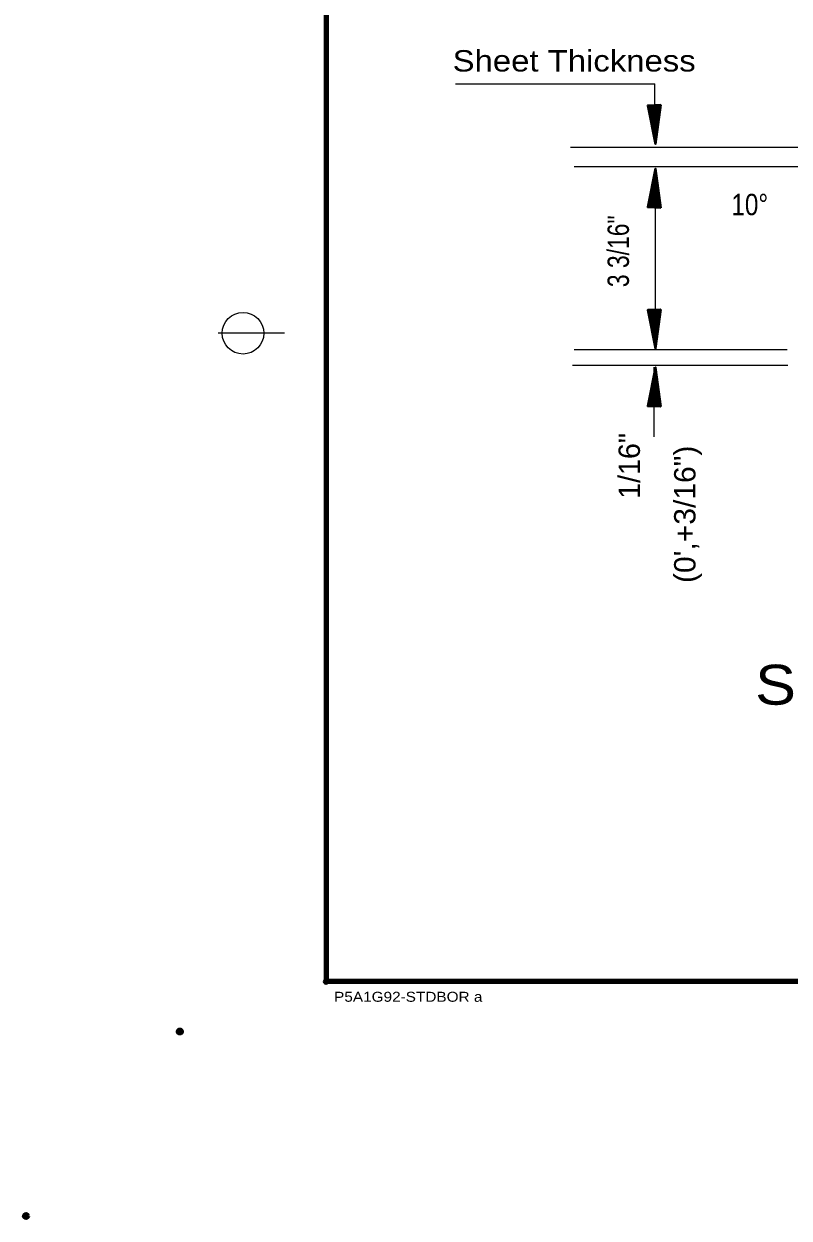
# Model space of a CAD drawing. Extents: x 895.6 to 930.4, y -2278.6 to -2254.7.
# Drawn here: x 895.62 to 900.23, y -2278.59 to -2271.4 of the extents above; entities that cross this region are included whole.
import ezdxf

# ---------------------------------------------------------------- set-up
doc = ezdxf.new("R2010")
doc.units = 0
doc.header["$LTSCALE"] = 0.051
doc.header["$PDMODE"] = 32
doc.header["$PDSIZE"] = 0.0255
doc.layers.add('1', color=7, linetype='Continuous', lineweight=70)
doc.layers.add('3', color=7, linetype='Continuous', lineweight=40)

msp = doc.modelspace()

# ---------------------------------------------------------------- hatches: boundary and pattern name
at = {"layer": '3'}
for points in [[(899.4545, -2271.89058), (899.3765, -2271.89325), (899.42342, -2272.12592), (899.42342, -2272.12592)], [(899.45058, -2271.89183), (899.38042, -2271.89417), (899.42258, -2272.1035), (899.42258, -2272.1035)], [(899.44708, -2271.89283), (899.384, -2271.895), (899.422, -2272.08342), (899.422, -2272.08342)], [(899.444, -2271.89383), (899.38725, -2271.89575), (899.42142, -2272.06533), (899.42142, -2272.06533)], [(899.44133, -2271.89458), (899.39017, -2271.89642), (899.42092, -2272.04908), (899.42092, -2272.04908)], [(899.43867, -2271.89558), (899.39267, -2271.89708), (899.42042, -2272.03442), (899.42042, -2272.03442)], [(899.43633, -2271.89617), (899.39492, -2271.8975), (899.41992, -2272.02125), (899.41992, -2272.02125)], [(899.43442, -2271.89692), (899.39708, -2271.898), (899.41958, -2272.00925), (899.41958, -2272.00925)], [(899.43258, -2271.89725), (899.39892, -2271.89858), (899.41908, -2271.99867), (899.41908, -2271.99867)], [(899.43083, -2271.89792), (899.4005, -2271.899), (899.41883, -2271.989), (899.41883, -2271.989)], [(899.42933, -2271.89842), (899.40217, -2271.89933), (899.4185, -2271.98033), (899.4185, -2271.98033)], [(899.42792, -2271.89875), (899.40358, -2271.89967), (899.41817, -2271.97258), (899.41817, -2271.97258)], [(899.42683, -2271.89925), (899.40475, -2271.89992), (899.418, -2271.96542), (899.418, -2271.96542)], [(899.42567, -2271.89967), (899.40583, -2271.90017), (899.41783, -2271.95933), (899.41783, -2271.95933)], [(899.42475, -2271.89992), (899.40683, -2271.9005), (899.41767, -2271.95358), (899.41767, -2271.95358)], [(899.42383, -2271.90017), (899.40767, -2271.90058), (899.41733, -2271.9485), (899.41733, -2271.9485)], [(899.423, -2271.90042), (899.40842, -2271.90092), (899.41717, -2271.94392), (899.41717, -2271.94392)], [(899.42225, -2271.90058), (899.40925, -2271.901), (899.41708, -2271.93983), (899.41708, -2271.93983)], [(899.42183, -2271.90092), (899.41, -2271.90117), (899.41708, -2271.93617), (899.41708, -2271.93617)], [(899.42125, -2271.90108), (899.41067, -2271.90142), (899.417, -2271.93292), (899.417, -2271.93292)], [(899.42092, -2271.90133), (899.41133, -2271.90167), (899.41717, -2271.92992), (899.41717, -2271.92992)], [(899.42033, -2271.90133), (899.41183, -2271.90167), (899.417, -2271.92717), (899.417, -2271.92717)], [(899.41983, -2271.9015), (899.41225, -2271.90183), (899.41675, -2271.92475), (899.41675, -2271.92475)], [(899.41958, -2271.90167), (899.41275, -2271.90192), (899.41683, -2271.92258), (899.41683, -2271.92258)], [(899.4545, -2272.50825), (899.3765, -2272.50558), (899.42342, -2272.27292), (899.42342, -2272.27292)], [(899.45058, -2272.507), (899.38042, -2272.50467), (899.42258, -2272.29533), (899.42258, -2272.29533)], [(899.44708, -2272.506), (899.384, -2272.50383), (899.422, -2272.31542), (899.422, -2272.31542)], [(899.444, -2272.505), (899.38725, -2272.50308), (899.42142, -2272.3335), (899.42142, -2272.3335)], [(899.44133, -2272.50425), (899.39017, -2272.50242), (899.42092, -2272.34975), (899.42092, -2272.34975)], [(899.43867, -2272.50325), (899.39267, -2272.50175), (899.42042, -2272.36442), (899.42042, -2272.36442)], [(899.43633, -2272.50267), (899.39492, -2272.50133), (899.41992, -2272.37758), (899.41992, -2272.37758)], [(899.43442, -2272.50192), (899.39708, -2272.50083), (899.41958, -2272.38958), (899.41958, -2272.38958)], [(899.43258, -2272.50158), (899.39892, -2272.50025), (899.41908, -2272.40017), (899.41908, -2272.40017)], [(899.43083, -2272.50092), (899.4005, -2272.49983), (899.41883, -2272.40983), (899.41883, -2272.40983)], [(899.42933, -2272.50042), (899.40217, -2272.4995), (899.4185, -2272.4185), (899.4185, -2272.4185)], [(899.42792, -2272.50008), (899.40358, -2272.49917), (899.41817, -2272.42625), (899.41817, -2272.42625)], [(899.42683, -2272.49958), (899.40475, -2272.49892), (899.418, -2272.43342), (899.418, -2272.43342)], [(899.42567, -2272.49917), (899.40583, -2272.49867), (899.41783, -2272.4395), (899.41783, -2272.4395)], [(899.42475, -2272.49892), (899.40683, -2272.49833), (899.41767, -2272.44525), (899.41767, -2272.44525)], [(899.42383, -2272.49867), (899.40767, -2272.49825), (899.41733, -2272.45033), (899.41733, -2272.45033)], [(899.423, -2272.49842), (899.40842, -2272.49792), (899.41717, -2272.45492), (899.41717, -2272.45492)], [(899.42225, -2272.49825), (899.40925, -2272.49783), (899.41708, -2272.459), (899.41708, -2272.459)], [(899.42183, -2272.49792), (899.41, -2272.49767), (899.41708, -2272.46267), (899.41708, -2272.46267)], [(899.42125, -2272.49775), (899.41067, -2272.49742), (899.417, -2272.46592), (899.417, -2272.46592)], [(899.42092, -2272.4975), (899.41133, -2272.49717), (899.41717, -2272.46892), (899.41717, -2272.46892)], [(899.42033, -2272.4975), (899.41183, -2272.49717), (899.417, -2272.47167), (899.417, -2272.47167)], [(899.41983, -2272.49733), (899.41225, -2272.497), (899.41675, -2272.47408), (899.41675, -2272.47408)], [(899.41958, -2272.49717), (899.41275, -2272.49692), (899.41683, -2272.47625), (899.41683, -2272.47625)], [(899.4545, -2273.12025), (899.3765, -2273.12292), (899.42342, -2273.35558), (899.42342, -2273.35558)], [(899.45058, -2273.1215), (899.38042, -2273.12383), (899.42258, -2273.33317), (899.42258, -2273.33317)], [(899.44708, -2273.1225), (899.384, -2273.12467), (899.422, -2273.31308), (899.422, -2273.31308)], [(899.444, -2273.1235), (899.38725, -2273.12542), (899.42142, -2273.295), (899.42142, -2273.295)], [(899.44133, -2273.12425), (899.39017, -2273.12608), (899.42092, -2273.27875), (899.42092, -2273.27875)], [(899.43867, -2273.12525), (899.39267, -2273.12675), (899.42042, -2273.26408), (899.42042, -2273.26408)], [(899.43633, -2273.12583), (899.39492, -2273.12717), (899.41992, -2273.25092), (899.41992, -2273.25092)], [(899.43442, -2273.12658), (899.39708, -2273.12767), (899.41958, -2273.23892), (899.41958, -2273.23892)], [(899.43258, -2273.12692), (899.39892, -2273.12825), (899.41908, -2273.22833), (899.41908, -2273.22833)], [(899.43083, -2273.12758), (899.4005, -2273.12867), (899.41883, -2273.21867), (899.41883, -2273.21867)], [(899.42933, -2273.12808), (899.40217, -2273.129), (899.4185, -2273.21), (899.4185, -2273.21)], [(899.42792, -2273.12842), (899.40358, -2273.12933), (899.41817, -2273.20225), (899.41817, -2273.20225)], [(899.42683, -2273.12892), (899.40475, -2273.12958), (899.418, -2273.19508), (899.418, -2273.19508)], [(899.42567, -2273.12933), (899.40583, -2273.12983), (899.41783, -2273.189), (899.41783, -2273.189)], [(899.42475, -2273.12958), (899.40683, -2273.13017), (899.41767, -2273.18325), (899.41767, -2273.18325)], [(899.42383, -2273.12983), (899.40767, -2273.13025), (899.41733, -2273.17817), (899.41733, -2273.17817)], [(899.423, -2273.13008), (899.40842, -2273.13058), (899.41717, -2273.17358), (899.41717, -2273.17358)], [(899.42225, -2273.13025), (899.40925, -2273.13067), (899.41708, -2273.1695), (899.41708, -2273.1695)], [(899.42183, -2273.13058), (899.41, -2273.13083), (899.41708, -2273.16583), (899.41708, -2273.16583)], [(899.42125, -2273.13075), (899.41067, -2273.13108), (899.417, -2273.16258), (899.417, -2273.16258)], [(899.42092, -2273.131), (899.41133, -2273.13133), (899.41717, -2273.15958), (899.41717, -2273.15958)], [(899.42033, -2273.131), (899.41183, -2273.13133), (899.417, -2273.15683), (899.417, -2273.15683)], [(899.41983, -2273.13117), (899.41225, -2273.1315), (899.41675, -2273.15442), (899.41675, -2273.15442)], [(899.41958, -2273.13133), (899.41275, -2273.13158), (899.41683, -2273.15225), (899.41683, -2273.15225)], [(899.4545, -2273.70475), (899.3765, -2273.70208), (899.42342, -2273.46942), (899.42342, -2273.46942)], [(899.45058, -2273.7035), (899.38042, -2273.70117), (899.42258, -2273.49183), (899.42258, -2273.49183)], [(899.44708, -2273.7025), (899.384, -2273.70033), (899.422, -2273.51192), (899.422, -2273.51192)], [(899.444, -2273.7015), (899.38725, -2273.69958), (899.42142, -2273.53), (899.42142, -2273.53)], [(899.44133, -2273.70075), (899.39017, -2273.69892), (899.42092, -2273.54625), (899.42092, -2273.54625)], [(899.43867, -2273.69975), (899.39267, -2273.69825), (899.42042, -2273.56092), (899.42042, -2273.56092)], [(899.43633, -2273.69917), (899.39492, -2273.69783), (899.41992, -2273.57408), (899.41992, -2273.57408)], [(899.43442, -2273.69842), (899.39708, -2273.69733), (899.41958, -2273.58608), (899.41958, -2273.58608)], [(899.43258, -2273.69808), (899.39892, -2273.69675), (899.41908, -2273.59667), (899.41908, -2273.59667)], [(899.43083, -2273.69742), (899.4005, -2273.69633), (899.41883, -2273.60633), (899.41883, -2273.60633)], [(899.42933, -2273.69692), (899.40217, -2273.696), (899.4185, -2273.615), (899.4185, -2273.615)], [(899.42792, -2273.69658), (899.40358, -2273.69567), (899.41817, -2273.62275), (899.41817, -2273.62275)], [(899.42683, -2273.69608), (899.40475, -2273.69542), (899.418, -2273.62992), (899.418, -2273.62992)], [(899.42567, -2273.69567), (899.40583, -2273.69517), (899.41783, -2273.636), (899.41783, -2273.636)], [(899.42475, -2273.69542), (899.40683, -2273.69483), (899.41767, -2273.64175), (899.41767, -2273.64175)], [(899.42383, -2273.69517), (899.40767, -2273.69475), (899.41733, -2273.64683), (899.41733, -2273.64683)], [(899.423, -2273.69492), (899.40842, -2273.69442), (899.41717, -2273.65142), (899.41717, -2273.65142)], [(899.42225, -2273.69475), (899.40925, -2273.69433), (899.41708, -2273.6555), (899.41708, -2273.6555)], [(899.42183, -2273.69442), (899.41, -2273.69417), (899.41708, -2273.65917), (899.41708, -2273.65917)], [(899.42125, -2273.69425), (899.41067, -2273.69392), (899.417, -2273.66242), (899.417, -2273.66242)], [(899.42092, -2273.694), (899.41133, -2273.69367), (899.41717, -2273.66542), (899.41717, -2273.66542)], [(899.42033, -2273.694), (899.41183, -2273.69367), (899.417, -2273.66817), (899.417, -2273.66817)], [(899.41983, -2273.69383), (899.41225, -2273.6935), (899.41675, -2273.67058), (899.41675, -2273.67058)], [(899.41958, -2273.69367), (899.41275, -2273.69342), (899.41683, -2273.67275), (899.41683, -2273.67275)]]:
    msp.add_hatch(color=256, dxfattribs=at).paths.add_polyline_path(points)

# ---------------------------------------------------------------- linework, layer by layer
at = {"layer": '1', "lineweight": 25}
for p, q in [((898.22108, -2271.76283), (899.41933, -2271.76283)), ((899.41933, -2272.12292), (899.41933, -2271.76283)), ((898.91175, -2272.14508), (900.7885, -2272.14508)), ((898.93392, -2272.26058), (900.6745, -2272.26058)), ((899.42375, -2273.33025), (899.42375, -2272.28775)), ((898.93392, -2273.36142), (900.21608, -2273.36142)), ((898.92433, -2273.45467), (900.21842, -2273.45467)), ((899.41483, -2273.88717), (899.41483, -2273.46842))]:
    msp.add_line(p, q, dxfattribs=at)
at = {"layer": '1'}
for p in [(896.56183, -2277.46333), (895.63642, -2278.57275)]:
    msp.add_point(p, dxfattribs=at)
at = {"layer": '3', "lineweight": 158}
msp.add_line((897.44183, -2256.16333), (897.44183, -2277.16333), dxfattribs=at)
at = {"layer": '3', "lineweight": 13}
msp.add_line((897.19183, -2273.26333), (896.79183, -2273.26333), dxfattribs=at)
at = {"layer": '3', "lineweight": 158}
msp.add_lwpolyline([(929.94183, -2256.16333), (929.94183, -2277.16333), (897.44183, -2277.16333)], dxfattribs=at)
at = {"layer": '3'}
for points in [[(899.4545, -2271.89058), (899.3765, -2271.89325), (899.42342, -2272.12592), (899.42342, -2272.12592)], [(899.45058, -2271.89183), (899.38042, -2271.89417), (899.42258, -2272.1035), (899.42258, -2272.1035)], [(899.44708, -2271.89283), (899.384, -2271.895), (899.422, -2272.08342), (899.422, -2272.08342)], [(899.444, -2271.89383), (899.38725, -2271.89575), (899.42142, -2272.06533), (899.42142, -2272.06533)], [(899.44133, -2271.89458), (899.39017, -2271.89642), (899.42092, -2272.04908), (899.42092, -2272.04908)], [(899.43867, -2271.89558), (899.39267, -2271.89708), (899.42042, -2272.03442), (899.42042, -2272.03442)], [(899.43633, -2271.89617), (899.39492, -2271.8975), (899.41992, -2272.02125), (899.41992, -2272.02125)], [(899.43442, -2271.89692), (899.39708, -2271.898), (899.41958, -2272.00925), (899.41958, -2272.00925)], [(899.43258, -2271.89725), (899.39892, -2271.89858), (899.41908, -2271.99867), (899.41908, -2271.99867)], [(899.43083, -2271.89792), (899.4005, -2271.899), (899.41883, -2271.989), (899.41883, -2271.989)], [(899.42933, -2271.89842), (899.40217, -2271.89933), (899.4185, -2271.98033), (899.4185, -2271.98033)], [(899.42792, -2271.89875), (899.40358, -2271.89967), (899.41817, -2271.97258), (899.41817, -2271.97258)], [(899.42683, -2271.89925), (899.40475, -2271.89992), (899.418, -2271.96542), (899.418, -2271.96542)], [(899.42567, -2271.89967), (899.40583, -2271.90017), (899.41783, -2271.95933), (899.41783, -2271.95933)], [(899.42475, -2271.89992), (899.40683, -2271.9005), (899.41767, -2271.95358), (899.41767, -2271.95358)], [(899.42383, -2271.90017), (899.40767, -2271.90058), (899.41733, -2271.9485), (899.41733, -2271.9485)], [(899.423, -2271.90042), (899.40842, -2271.90092), (899.41717, -2271.94392), (899.41717, -2271.94392)], [(899.42225, -2271.90058), (899.40925, -2271.901), (899.41708, -2271.93983), (899.41708, -2271.93983)], [(899.42183, -2271.90092), (899.41, -2271.90117), (899.41708, -2271.93617), (899.41708, -2271.93617)], [(899.42125, -2271.90108), (899.41067, -2271.90142), (899.417, -2271.93292), (899.417, -2271.93292)], [(899.42092, -2271.90133), (899.41133, -2271.90167), (899.41717, -2271.92992), (899.41717, -2271.92992)], [(899.42033, -2271.90133), (899.41183, -2271.90167), (899.417, -2271.92717), (899.417, -2271.92717)], [(899.41983, -2271.9015), (899.41225, -2271.90183), (899.41675, -2271.92475), (899.41675, -2271.92475)], [(899.41958, -2271.90167), (899.41275, -2271.90192), (899.41683, -2271.92258), (899.41683, -2271.92258)], [(899.4545, -2272.50825), (899.3765, -2272.50558), (899.42342, -2272.27292), (899.42342, -2272.27292)], [(899.45058, -2272.507), (899.38042, -2272.50467), (899.42258, -2272.29533), (899.42258, -2272.29533)], [(899.44708, -2272.506), (899.384, -2272.50383), (899.422, -2272.31542), (899.422, -2272.31542)], [(899.444, -2272.505), (899.38725, -2272.50308), (899.42142, -2272.3335), (899.42142, -2272.3335)], [(899.44133, -2272.50425), (899.39017, -2272.50242), (899.42092, -2272.34975), (899.42092, -2272.34975)], [(899.43867, -2272.50325), (899.39267, -2272.50175), (899.42042, -2272.36442), (899.42042, -2272.36442)], [(899.43633, -2272.50267), (899.39492, -2272.50133), (899.41992, -2272.37758), (899.41992, -2272.37758)], [(899.43442, -2272.50192), (899.39708, -2272.50083), (899.41958, -2272.38958), (899.41958, -2272.38958)], [(899.43258, -2272.50158), (899.39892, -2272.50025), (899.41908, -2272.40017), (899.41908, -2272.40017)], [(899.43083, -2272.50092), (899.4005, -2272.49983), (899.41883, -2272.40983), (899.41883, -2272.40983)], [(899.42933, -2272.50042), (899.40217, -2272.4995), (899.4185, -2272.4185), (899.4185, -2272.4185)], [(899.42792, -2272.50008), (899.40358, -2272.49917), (899.41817, -2272.42625), (899.41817, -2272.42625)], [(899.42683, -2272.49958), (899.40475, -2272.49892), (899.418, -2272.43342), (899.418, -2272.43342)], [(899.42567, -2272.49917), (899.40583, -2272.49867), (899.41783, -2272.4395), (899.41783, -2272.4395)], [(899.42475, -2272.49892), (899.40683, -2272.49833), (899.41767, -2272.44525), (899.41767, -2272.44525)], [(899.42383, -2272.49867), (899.40767, -2272.49825), (899.41733, -2272.45033), (899.41733, -2272.45033)], [(899.423, -2272.49842), (899.40842, -2272.49792), (899.41717, -2272.45492), (899.41717, -2272.45492)], [(899.42225, -2272.49825), (899.40925, -2272.49783), (899.41708, -2272.459), (899.41708, -2272.459)], [(899.42183, -2272.49792), (899.41, -2272.49767), (899.41708, -2272.46267), (899.41708, -2272.46267)], [(899.42125, -2272.49775), (899.41067, -2272.49742), (899.417, -2272.46592), (899.417, -2272.46592)], [(899.42092, -2272.4975), (899.41133, -2272.49717), (899.41717, -2272.46892), (899.41717, -2272.46892)], [(899.42033, -2272.4975), (899.41183, -2272.49717), (899.417, -2272.47167), (899.417, -2272.47167)], [(899.41983, -2272.49733), (899.41225, -2272.497), (899.41675, -2272.47408), (899.41675, -2272.47408)], [(899.41958, -2272.49717), (899.41275, -2272.49692), (899.41683, -2272.47625), (899.41683, -2272.47625)], [(899.4545, -2273.12025), (899.3765, -2273.12292), (899.42342, -2273.35558), (899.42342, -2273.35558)], [(899.45058, -2273.1215), (899.38042, -2273.12383), (899.42258, -2273.33317), (899.42258, -2273.33317)], [(899.44708, -2273.1225), (899.384, -2273.12467), (899.422, -2273.31308), (899.422, -2273.31308)], [(899.444, -2273.1235), (899.38725, -2273.12542), (899.42142, -2273.295), (899.42142, -2273.295)], [(899.44133, -2273.12425), (899.39017, -2273.12608), (899.42092, -2273.27875), (899.42092, -2273.27875)], [(899.43867, -2273.12525), (899.39267, -2273.12675), (899.42042, -2273.26408), (899.42042, -2273.26408)], [(899.43633, -2273.12583), (899.39492, -2273.12717), (899.41992, -2273.25092), (899.41992, -2273.25092)], [(899.43442, -2273.12658), (899.39708, -2273.12767), (899.41958, -2273.23892), (899.41958, -2273.23892)], [(899.43258, -2273.12692), (899.39892, -2273.12825), (899.41908, -2273.22833), (899.41908, -2273.22833)], [(899.43083, -2273.12758), (899.4005, -2273.12867), (899.41883, -2273.21867), (899.41883, -2273.21867)], [(899.42933, -2273.12808), (899.40217, -2273.129), (899.4185, -2273.21), (899.4185, -2273.21)], [(899.42792, -2273.12842), (899.40358, -2273.12933), (899.41817, -2273.20225), (899.41817, -2273.20225)], [(899.42683, -2273.12892), (899.40475, -2273.12958), (899.418, -2273.19508), (899.418, -2273.19508)], [(899.42567, -2273.12933), (899.40583, -2273.12983), (899.41783, -2273.189), (899.41783, -2273.189)], [(899.42475, -2273.12958), (899.40683, -2273.13017), (899.41767, -2273.18325), (899.41767, -2273.18325)], [(899.42383, -2273.12983), (899.40767, -2273.13025), (899.41733, -2273.17817), (899.41733, -2273.17817)], [(899.423, -2273.13008), (899.40842, -2273.13058), (899.41717, -2273.17358), (899.41717, -2273.17358)], [(899.42225, -2273.13025), (899.40925, -2273.13067), (899.41708, -2273.1695), (899.41708, -2273.1695)], [(899.42183, -2273.13058), (899.41, -2273.13083), (899.41708, -2273.16583), (899.41708, -2273.16583)], [(899.42125, -2273.13075), (899.41067, -2273.13108), (899.417, -2273.16258), (899.417, -2273.16258)], [(899.42092, -2273.131), (899.41133, -2273.13133), (899.41717, -2273.15958), (899.41717, -2273.15958)], [(899.42033, -2273.131), (899.41183, -2273.13133), (899.417, -2273.15683), (899.417, -2273.15683)], [(899.41983, -2273.13117), (899.41225, -2273.1315), (899.41675, -2273.15442), (899.41675, -2273.15442)], [(899.41958, -2273.13133), (899.41275, -2273.13158), (899.41683, -2273.15225), (899.41683, -2273.15225)], [(899.4545, -2273.70475), (899.3765, -2273.70208), (899.42342, -2273.46942), (899.42342, -2273.46942)], [(899.45058, -2273.7035), (899.38042, -2273.70117), (899.42258, -2273.49183), (899.42258, -2273.49183)], [(899.44708, -2273.7025), (899.384, -2273.70033), (899.422, -2273.51192), (899.422, -2273.51192)], [(899.444, -2273.7015), (899.38725, -2273.69958), (899.42142, -2273.53), (899.42142, -2273.53)], [(899.44133, -2273.70075), (899.39017, -2273.69892), (899.42092, -2273.54625), (899.42092, -2273.54625)], [(899.43867, -2273.69975), (899.39267, -2273.69825), (899.42042, -2273.56092), (899.42042, -2273.56092)], [(899.43633, -2273.69917), (899.39492, -2273.69783), (899.41992, -2273.57408), (899.41992, -2273.57408)], [(899.43442, -2273.69842), (899.39708, -2273.69733), (899.41958, -2273.58608), (899.41958, -2273.58608)], [(899.43258, -2273.69808), (899.39892, -2273.69675), (899.41908, -2273.59667), (899.41908, -2273.59667)], [(899.43083, -2273.69742), (899.4005, -2273.69633), (899.41883, -2273.60633), (899.41883, -2273.60633)], [(899.42933, -2273.69692), (899.40217, -2273.696), (899.4185, -2273.615), (899.4185, -2273.615)], [(899.42792, -2273.69658), (899.40358, -2273.69567), (899.41817, -2273.62275), (899.41817, -2273.62275)], [(899.42683, -2273.69608), (899.40475, -2273.69542), (899.418, -2273.62992), (899.418, -2273.62992)], [(899.42567, -2273.69567), (899.40583, -2273.69517), (899.41783, -2273.636), (899.41783, -2273.636)], [(899.42475, -2273.69542), (899.40683, -2273.69483), (899.41767, -2273.64175), (899.41767, -2273.64175)], [(899.42383, -2273.69517), (899.40767, -2273.69475), (899.41733, -2273.64683), (899.41733, -2273.64683)], [(899.423, -2273.69492), (899.40842, -2273.69442), (899.41717, -2273.65142), (899.41717, -2273.65142)], [(899.42225, -2273.69475), (899.40925, -2273.69433), (899.41708, -2273.6555), (899.41708, -2273.6555)], [(899.42183, -2273.69442), (899.41, -2273.69417), (899.41708, -2273.65917), (899.41708, -2273.65917)], [(899.42125, -2273.69425), (899.41067, -2273.69392), (899.417, -2273.66242), (899.417, -2273.66242)], [(899.42092, -2273.694), (899.41133, -2273.69367), (899.41717, -2273.66542), (899.41717, -2273.66542)], [(899.42033, -2273.694), (899.41183, -2273.69367), (899.417, -2273.66817), (899.417, -2273.66817)], [(899.41983, -2273.69383), (899.41225, -2273.6935), (899.41675, -2273.67058), (899.41675, -2273.67058)], [(899.41958, -2273.69367), (899.41275, -2273.69342), (899.41683, -2273.67275), (899.41683, -2273.67275)]]:
    msp.add_lwpolyline(points, close=True, dxfattribs=at)
at = {"layer": '3', "lineweight": 13}
msp.add_circle((896.94183, -2273.26333), 0.125, dxfattribs=at)
at = {"layer": '3'}
msp.add_point((897.44183, -2277.16333), dxfattribs=at)

# ---------------------------------------------------------------- texts
at = {"layer": '1'}
for s, height, width, p in [('Sheet Thickness', 0.1286, 1.15, (898.20292, -2271.68933)), ('10°', 0.1286, 0.85, (899.87967, -2272.5535)), ('SECTION THRU THRIE BEAM RAIL ELEMENT', 0.24, 1.15, (900.02233, -2275.49725))]:
    msp.add_text(s, height=height, dxfattribs=dict(at, width=width)).set_placement(p)
for s, width, p in [('3 3/16"', 0.8, (899.2635, -2272.98608)), ('(0\',+3/16")', 1.05, (899.66375, -2274.76567))]:
    msp.add_text(s, height=0.1286, rotation=90, dxfattribs=dict(at, width=width)).set_placement(p)
msp.add_text('1/16" ', height=0.1286, rotation=90, dxfattribs=at).set_placement((899.32958, -2274.25917))
at = {"layer": '3', "width": 1.15}
msp.add_text('P5A1G92-STDBOR a', height=0.06, dxfattribs=at).set_placement((897.48983, -2277.28433))

doc.saveas('drawing.dxf')
